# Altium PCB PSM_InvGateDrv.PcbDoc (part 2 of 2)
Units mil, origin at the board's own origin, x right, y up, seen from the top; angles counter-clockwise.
Board outline 5413.39 x 1771.65 mil, 2 copper layers (Top Layer, Bottom Layer), stack 62 mil thick; 130 components, 58 nets, 317 pads, 172 vias.
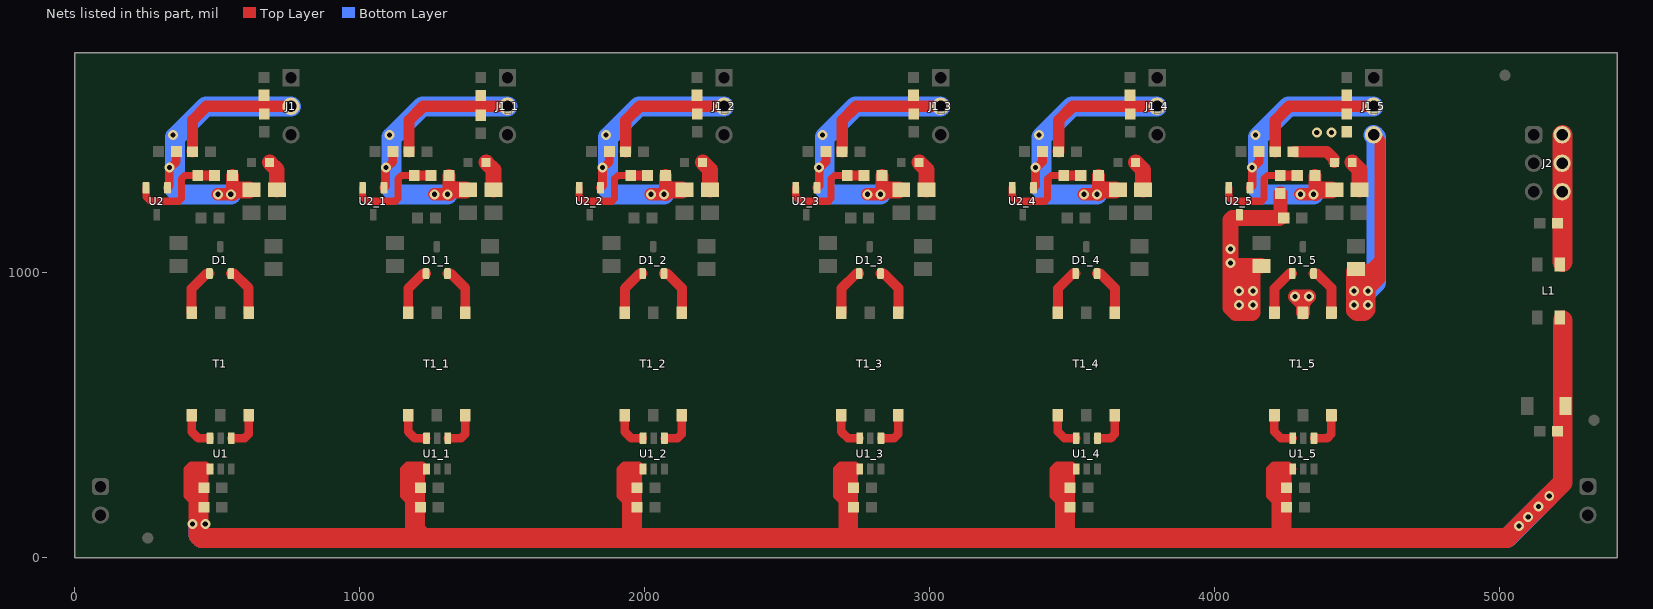
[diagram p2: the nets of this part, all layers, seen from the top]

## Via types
v1: diameter 35, hole 18, Top Layer to Bottom Layer, 172 vias

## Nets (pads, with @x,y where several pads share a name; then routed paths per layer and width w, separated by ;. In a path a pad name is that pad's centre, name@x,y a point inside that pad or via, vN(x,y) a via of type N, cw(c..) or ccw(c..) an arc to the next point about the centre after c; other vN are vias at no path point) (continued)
-4V_6: C4_5.2 C5_5.2 C6_5.2 C7_5.2 C10_5.2 D2_5.1 J1_5.3 R4_5.1 T1_5.5 U2_5.3 | length 2935.9
  Top Layer w40: C6_5.2@4234.67,1200.1 C6_5.2@4243.04,1191.73 ; C10_5.2@4282.41,1424.55 4394.08,1424.55 4420.6,1398.03 D2_5.1@4420.6,1387.15 ; v1(4538.31,935.83) 4580.95,978.46 4580.95,1043.31 ; 4538.31,1004.72 4542.36,1004.72 4580.95,1043.31 ; J1_5.3@4558.63,1484 4580.95,1461.68 4580.95,1043.31
  Top Layer w50: C6_5.2@4226.31,1191.73 4231.33,1196.75 R4_5.1@4231.33,1278.35 ; T1_5.5@4310.26,859.84 4310.26,888.29 ; 4310.26,888.29 4310.26,894.78 v1(4331.62,916.14) v1(4282.41,916.14) 4310.26,888.29
  Top Layer w55: 4085.56,992.91 v1(4085.56,935.83) v1(4085.56,886.61) 4085.56,857.09 ; 4134.77,989.78 v1(4134.77,935.83) v1(4134.77,886.61) 4134.77,859.84 4132.02,857.09 4085.56,857.09 ; C4_5.2@4164.3,1023.78 v1@4056.03,1023.78 ; C6_5.2@4226.31,1191.73 4063.12,1191.73 4056.03,1184.65 v1@4056.03,1023.78 ; v1@4056.03,1023.78 4056.03,876.77 4075.72,857.09 4085.56,857.09 ; 4489.1,866.93 4498.94,857.09 4525.72,857.09 4538.31,869.69 v1(4538.31,886.61) v1(4538.31,935.83) 4538.31,1004.72 4489.1,1004.72 v1(4489.1,935.83) v1(4489.1,886.61) 4489.1,866.93
  Bottom Layer w70: v1(4538.31,935.83) 4567.84,965.35 4567.84,1474.79 J1_5.3@4558.63,1484
  other v1: 4056.03,1034.25 4056.03,1083.46 4359.18,1492.02 4410.76,1492.02
AGND: C2.2 C2_1.2 C2_2.2 C2_3.2 C2_4.2 C2_5.2 C3.2 C3_1.2 C3_2.2 C3_3.2 C3_4.2 C3_5.2 C8.2 C12.2 L1.2 U1.4 U1_1.4 U1_2.4 U1_3.4 U1_4.4 U1_5.4 | length 13894.7
  Top Layer w25: 423.35,187.32 393.83,216.85 393.83,310.83 408.12,325.12 460.24,325.12 U1.4@474.54,310.83 452.88,289.17 C3.2@452.88,245.42 C2.2@452.88,176.52 ; 1183.35,187.32 1153.83,216.85 1153.83,310.83 1168.12,325.12 1220.24,325.12 U1_1.4@1234.54,310.83 1212.88,289.17 C3_1.2@1212.88,245.42 C2_1.2@1212.88,176.52 ; 1943.35,187.32 1913.83,216.85 1913.83,310.83 1928.12,325.12 1980.24,325.12 U1_2.4@1994.54,310.83 1972.88,289.17 C3_2.2@1972.88,245.42 C2_2.2@1972.88,176.52 ; 2703.35,187.32 2673.83,216.85 2673.83,310.83 2688.12,325.12 2740.24,325.12 U1_3.4@2754.54,310.83 2732.88,289.17 C3_3.2@2732.88,245.42 C2_3.2@2732.88,176.52 ; 3463.35,187.32 3433.83,216.85 3433.83,310.83 3448.12,325.12 3500.24,325.12 U1_4.4@3514.54,310.83 3492.88,289.17 C3_4.2@3492.88,245.42 C2_4.2@3492.88,176.52 ; 4223.35,187.32 4193.83,216.85 4193.83,310.83 4208.12,325.12 4260.24,325.12 U1_5.4@4274.54,310.83 4252.88,289.17 C3_5.2@4252.88,245.42 C2_5.2@4252.88,176.52
  Top Layer w70: 434.67,299.19 434.67,176.52 434.67,78.71 444.98,68.41 1222.99,68.41 ; C3_1.2@1193.63,245.42 1193.63,289.35 ; C3_1.2@1194.67,245.42 1194.67,96.73 1222.99,68.41 ; 1954.94,79.05 1954.94,299.53 ; 2714.67,299.19 2714.67,245.42 2714.67,78.71 2724.98,68.41 ; 3474.67,299.19 3474.67,245.42 3474.67,78.71 3484.98,68.41 ; 4234.67,68.41 5026.87,68.41 5222.38,263.91 5222.38,442.91 5222.38,531.5 L1.2@5222.38,832.11 ; 4234.67,299.19 4234.67,245.42 4234.67,78.71 4244.98,68.41 3484.98,68.41 ; 1222.99,68.41 2724.98,68.41 ; 2724.98,68.41 3484.98,68.41
  Bottom Layer w70: 434.67,108.27 434.67,78.71 444.49,68.9 5027.36,68.9 v1(5175,216.54)
  other v1: 5068.9,110.43 413.51,118.11 457.88,118.11 5101.18,142.72 5137.8,179.33
NetC11_2: C11.2 J2.2 J2.4 J2.6 L1.3 | length 446
  Top Layer w70: L1.3@5220.8,1037.97 5220.8,1284 5220.8,1384 J2.2@5220.8,1484
NetD1_1: D1.1 T1.6 | length 168.7
  Top Layer w35: T1.6@410.26,859.84 410.26,944.09 463.02,996.85 D1.1@472.86,996.85
NetD1_1_1: D1_1.1 T1_1.6 | length 168.7
  Top Layer w35: T1_1.6@1170.26,859.84 1170.26,944.09 1223.02,996.85 D1_1.1@1232.86,996.85
NetD1_1_2: D1_1.2 T1_1.4 | length 169.7
  Top Layer w35: D1_1.2@1307.67,996.85 1319.18,996.85 1370.26,945.77 T1_1.4@1370.26,859.84
NetD1_2: D1.2 T1.4 | length 169.7
  Top Layer w35: D1.2@547.67,996.85 559.18,996.85 610.26,945.77 T1.4@610.26,859.84
NetD1_2_1: D1_2.1 T1_2.6 | length 168.7
  Top Layer w35: T1_2.6@1930.26,859.84 1930.26,944.09 1983.02,996.85 D1_2.1@1992.86,996.85
NetD1_2_2: D1_2.2 T1_2.4 | length 169.7
  Top Layer w35: D1_2.2@2067.67,996.85 2079.18,996.85 2130.26,945.77 T1_2.4@2130.26,859.84
NetD1_3_1: D1_3.1 T1_3.6 | length 168.7
  Top Layer w35: T1_3.6@2690.26,859.84 2690.26,944.09 2743.02,996.85 D1_3.1@2752.86,996.85
NetD1_3_2: D1_3.2 T1_3.4 | length 169.7
  Top Layer w35: D1_3.2@2827.67,996.85 2839.18,996.85 2890.26,945.77 T1_3.4@2890.26,859.84
NetD1_4_1: D1_4.1 T1_4.6 | length 168.7
  Top Layer w35: T1_4.6@3450.26,859.84 3450.26,944.09 3503.02,996.85 D1_4.1@3512.86,996.85
NetD1_4_2: D1_4.2 T1_4.4 | length 169.7
  Top Layer w35: D1_4.2@3587.67,996.85 3599.18,996.85 3650.26,945.77 T1_4.4@3650.26,859.84
NetD1_5_1: D1_5.1 T1_5.6 | length 168.7
  Top Layer w35: T1_5.6@4210.26,859.84 4210.26,944.09 4263.02,996.85 D1_5.1@4272.86,996.85
NetD1_5_2: D1_5.2 T1_5.4 | length 169.7
  Top Layer w35: D1_5.2@4347.67,996.85 4359.18,996.85 4410.26,945.77 T1_5.4@4410.26,859.84
NetD2_1_2: D2_1.2 R1_1.1 | length 107
  Top Layer w55: D2_1.2@1443.59,1387.15 1469.18,1361.56 R1_1.1@1469.18,1290.79
NetD2_2: D2.2 R1.1 | length 107
  Top Layer w55: D2.2@683.59,1387.15 709.18,1361.56 R1.1@709.18,1290.79
NetD2_2_2: D2_2.2 R1_2.1 | length 107
  Top Layer w55: D2_2.2@2203.59,1387.15 2229.18,1361.56 R1_2.1@2229.18,1290.79
NetD2_3_2: D2_3.2 R1_3.1 | length 107
  Top Layer w55: D2_3.2@2963.59,1387.15 2989.18,1361.56 R1_3.1@2989.18,1290.79
NetD2_4_2: D2_4.2 R1_4.1 | length 107
  Top Layer w55: D2_4.2@3723.59,1387.15 3749.18,1361.56 R1_4.1@3749.18,1290.79
NetD2_5_2: D2_5.2 R1_5.1 | length 107
  Top Layer w55: D2_5.2@4483.59,1387.15 4509.18,1361.56 R1_5.1@4509.18,1290.79
NetR3_1: R3.1 R4.2 U2.2 | length 350.1
  Top Layer w25: U2.2@250.13,1298.03 250.13,1266.54 265.87,1250.79 364.3,1250.79 374.14,1260.63 374.14,1329.53 385.95,1341.34 R4.2@431.33,1341.34
  Top Layer w35: R4.2@431.33,1341.34 R3.1@484.38,1341.34
NetR3_1_1: R3_1.1 R4_1.2 U2_1.2 | length 350.1
  Top Layer w25: U2_1.2@1010.13,1298.03 1010.13,1266.54 1025.87,1250.79 1124.3,1250.79 1134.14,1260.63 1134.14,1329.53 1145.95,1341.34 R4_1.2@1191.33,1341.34
  Top Layer w35: R4_1.2@1191.33,1341.34 R3_1.1@1244.38,1341.34
NetR3_2_1: R3_2.1 R4_2.2 U2_2.2 | length 350.1
  Top Layer w25: U2_2.2@1770.13,1298.03 1770.13,1266.54 1785.87,1250.79 1884.3,1250.79 1894.14,1260.63 1894.14,1329.53 1905.95,1341.34 R4_2.2@1951.33,1341.34
  Top Layer w35: R4_2.2@1951.33,1341.34 R3_2.1@2004.38,1341.34
NetR3_3_1: R3_3.1 R4_3.2 U2_3.2 | length 350.1
  Top Layer w25: U2_3.2@2530.13,1298.03 2530.13,1266.54 2545.87,1250.79 2644.3,1250.79 2654.14,1260.63 2654.14,1329.53 2665.95,1341.34 R4_3.2@2711.33,1341.34
  Top Layer w35: R4_3.2@2711.33,1341.34 R3_3.1@2764.38,1341.34
NetR3_4_1: R3_4.1 R4_4.2 U2_4.2 | length 350.1
  Top Layer w25: U2_4.2@3290.13,1298.03 3290.13,1266.54 3305.87,1250.79 3404.3,1250.79 3414.14,1260.63 3414.14,1329.53 3425.95,1341.34 R4_4.2@3471.33,1341.34
  Top Layer w35: R4_4.2@3471.33,1341.34 R3_4.1@3524.38,1341.34
NetR3_5_1: R3_5.1 R4_5.2 U2_5.2 | length 350.1
  Top Layer w25: U2_5.2@4050.13,1298.03 4050.13,1266.54 4065.87,1250.79 4164.3,1250.79 4174.14,1260.63 4174.14,1329.53 4185.95,1341.34 R4_5.2@4231.33,1341.34
  Top Layer w35: R4_5.2@4231.33,1341.34 R3_5.1@4284.38,1341.34
NetT1_1: T1.1 U1.3 | length 131.3
  Top Layer w30: T1.1@410.26,500 410.26,442.03 433.2,419.09 U1.3@474.06,419.09
NetT1_1_1: T1_1.1 U1_1.3 | length 131.3
  Top Layer w30: T1_1.1@1170.26,500 1170.26,442.03 1193.2,419.09 U1_1.3@1234.06,419.09
NetT1_1_3: T1_1.3 U1_1.1 | length 132.8
  Top Layer w30: U1_1.1@1309.81,419.09 1355.6,419.09 1370.26,433.76 T1_1.3@1370.26,500
NetT1_2_1: T1_2.1 U1_2.3 | length 131.3
  Top Layer w30: T1_2.1@1930.26,500 1930.26,442.03 1953.2,419.09 U1_2.3@1994.06,419.09
NetT1_2_3: T1_2.3 U1_2.1 | length 132.8
  Top Layer w30: U1_2.1@2069.81,419.09 2115.6,419.09 2130.26,433.76 T1_2.3@2130.26,500
NetT1_3: T1.3 U1.1 | length 132.8
  Top Layer w30: U1.1@549.81,419.09 595.6,419.09 610.26,433.76 T1.3@610.26,500
NetT1_3_1: T1_3.1 U1_3.3 | length 131.3
  Top Layer w30: T1_3.1@2690.26,500 2690.26,442.03 2713.2,419.09 U1_3.3@2754.06,419.09
NetT1_3_3: T1_3.3 U1_3.1 | length 132.8
  Top Layer w30: U1_3.1@2829.81,419.09 2875.6,419.09 2890.26,433.76 T1_3.3@2890.26,500
NetT1_4_1: T1_4.1 U1_4.3 | length 131.3
  Top Layer w30: T1_4.1@3450.26,500 3450.26,442.03 3473.2,419.09 U1_4.3@3514.06,419.09
NetT1_4_3: T1_4.3 U1_4.1 | length 132.8
  Top Layer w30: U1_4.1@3589.81,419.09 3635.6,419.09 3650.26,433.76 T1_4.3@3650.26,500
NetT1_5_1: T1_5.1 U1_5.3 | length 131.3
  Top Layer w30: T1_5.1@4210.26,500 4210.26,442.03 4233.2,419.09 U1_5.3@4274.06,419.09
NetT1_5_3: T1_5.3 U1_5.1 | length 132.8
  Top Layer w30: U1_5.1@4349.81,419.09 4395.6,419.09 4410.26,433.76 T1_5.3@4410.26,500
S_1: C1.2 C7.1 C9.2 C10.1 J1.2 R2.1 R3.2 U2.1 | length 1632.6
  Top Layer w30: U2.1@324.93,1298.03 332.02,1305.12 v1(332.02,1368.72) 336.02,1368.72 356.43,1389.12 C9.2@356.43,1425.54
  Top Layer w40: C10.1@412.04,1425.54 C10.1@413.02,1424.55 413.02,1495.87 413.02,1534.44 462.58,1584 J1.2@758.63,1584
  Top Layer w45: v1(502.09,1275.2) v1(547.37,1275.2) 553.28,1281.1 R3.2@553.28,1341.34
  Top Layer w60: v1@553.28,1281.1 562.96,1290.79 R2.1@610.76,1290.79
  Bottom Layer w70: v1(547.37,1275.2) v1(502.09,1275.2) 369.42,1275.2 352.09,1292.52 352.09,1475.59 460.5,1584 J1.2@758.63,1584
  other v1: 344.49,1483.87
S_2: C1_1.2 C7_1.1 C9_1.2 C10_1.1 J1_1.2 R2_1.1 R3_1.2 U2_1.1 | length 1632.6
  Top Layer w30: U2_1.1@1084.93,1298.03 1092.02,1305.12 v1(1092.02,1368.72) 1096.02,1368.72 1116.43,1389.12 C9_1.2@1116.43,1425.54
  Top Layer w40: C10_1.1@1172.04,1425.54 C10_1.1@1173.02,1424.55 1173.02,1495.87 1173.02,1534.44 1222.58,1584 J1_1.2@1518.63,1584
  Top Layer w45: v1(1262.09,1275.2) v1(1307.37,1275.2) 1313.28,1281.1 R3_1.2@1313.28,1341.34
  Top Layer w60: v1@1313.28,1281.1 1322.96,1290.79 R2_1.1@1370.76,1290.79
  Bottom Layer w70: v1(1307.37,1275.2) v1(1262.09,1275.2) 1129.42,1275.2 1112.09,1292.52 1112.09,1475.59 1220.5,1584 J1_1.2@1518.63,1584
  other v1: 1104.49,1483.87
S_3: C1_2.2 C7_2.1 C9_2.2 C10_2.1 J1_2.2 R2_2.1 R3_2.2 U2_2.1 | length 1632.6
  Top Layer w30: U2_2.1@1844.93,1298.03 1852.02,1305.12 v1(1852.02,1368.72) 1856.02,1368.72 1876.43,1389.12 C9_2.2@1876.43,1425.54
  Top Layer w40: C10_2.1@1932.04,1425.54 C10_2.1@1933.02,1424.55 1933.02,1495.87 1933.02,1534.44 1982.58,1584 J1_2.2@2278.63,1584
  Top Layer w45: v1(2022.09,1275.2) v1(2067.37,1275.2) 2073.28,1281.1 R3_2.2@2073.28,1341.34
  Top Layer w60: v1@2073.28,1281.1 2082.96,1290.79 R2_2.1@2130.76,1290.79
  Bottom Layer w70: v1(2067.37,1275.2) v1(2022.09,1275.2) 1889.42,1275.2 1872.09,1292.52 1872.09,1475.59 1980.5,1584 J1_2.2@2278.63,1584
  other v1: 1864.49,1483.87
S_4: C1_3.2 C7_3.1 C9_3.2 C10_3.1 J1_3.2 R2_3.1 R3_3.2 U2_3.1 | length 1632.6
  Top Layer w30: U2_3.1@2604.93,1298.03 2612.02,1305.12 v1(2612.02,1368.72) 2616.02,1368.72 2636.43,1389.12 C9_3.2@2636.43,1425.54
  Top Layer w40: C10_3.1@2692.04,1425.54 C10_3.1@2693.02,1424.55 2693.02,1495.87 2693.02,1534.44 2742.58,1584 J1_3.2@3038.63,1584
  Top Layer w45: v1(2782.09,1275.2) v1(2827.37,1275.2) 2833.28,1281.1 R3_3.2@2833.28,1341.34
  Top Layer w60: v1@2833.28,1281.1 2842.96,1290.79 R2_3.1@2890.76,1290.79
  Bottom Layer w70: v1(2827.37,1275.2) v1(2782.09,1275.2) 2649.42,1275.2 2632.09,1292.52 2632.09,1475.59 2740.5,1584 J1_3.2@3038.63,1584
  other v1: 2624.49,1483.87
S_5: C1_4.2 C7_4.1 C9_4.2 C10_4.1 J1_4.2 R2_4.1 R3_4.2 U2_4.1 | length 1632.6
  Top Layer w30: U2_4.1@3364.93,1298.03 3372.02,1305.12 v1(3372.02,1368.72) 3376.02,1368.72 3396.43,1389.12 C9_4.2@3396.43,1425.54
  Top Layer w40: C10_4.1@3452.04,1425.54 C10_4.1@3453.02,1424.55 3453.02,1495.87 3453.02,1534.44 3502.58,1584 J1_4.2@3798.63,1584
  Top Layer w45: v1(3542.09,1275.2) v1(3587.37,1275.2) 3593.28,1281.1 R3_4.2@3593.28,1341.34
  Top Layer w60: v1@3593.28,1281.1 3602.96,1290.79 R2_4.1@3650.76,1290.79
  Bottom Layer w70: v1(3587.37,1275.2) v1(3542.09,1275.2) 3409.42,1275.2 3392.09,1292.52 3392.09,1475.59 3500.5,1584 J1_4.2@3798.63,1584
  other v1: 3384.49,1483.87
S_6: C1_5.2 C7_5.1 C9_5.2 C10_5.1 J1_5.2 R2_5.1 R3_5.2 U2_5.1 | length 1632.6
  Top Layer w30: U2_5.1@4124.93,1298.03 4132.02,1305.12 v1(4132.02,1368.72) 4136.02,1368.72 4156.43,1389.12 C9_5.2@4156.43,1425.54
  Top Layer w40: C10_5.1@4212.04,1425.54 C10_5.1@4213.02,1424.55 4213.02,1495.87 4213.02,1534.44 4262.58,1584 J1_5.2@4558.63,1584
  Top Layer w45: v1(4302.09,1275.2) v1(4347.37,1275.2) 4353.28,1281.1 R3_5.2@4353.28,1341.34
  Top Layer w60: v1@4353.28,1281.1 4362.96,1290.79 R2_5.1@4410.76,1290.79
  Bottom Layer w70: v1(4347.37,1275.2) v1(4302.09,1275.2) 4169.42,1275.2 4152.09,1292.52 4152.09,1475.59 4260.5,1584 J1_5.2@4558.63,1584
  other v1: 4144.49,1483.87
pads on no net: FID1.1 FID2.1 FID3.1 J3.1 J3.2 J4.1 J4.2 U1.6 U1_1.6 U1_2.6 U1_3.6 U1_4.6 U1_5.6

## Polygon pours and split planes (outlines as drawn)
5Vs on Top Layer "TOP_LAYER_5VS_P098" (solid, pour order 98): 511.81,265.51 513.44,267.14 610.24,267.14 629.92,247.46 629.92,153.63 615.48,139.19 520.6,139.19 501.97,157.82 501.97,252.45 516.66,267.14
5Vs on Top Layer "TOP_LAYER_5VS_P096" (solid, pour order 96): 1270.63,265.51 1272.26,267.14 1369.06,267.14 1388.74,247.46 1388.74,153.63 1374.3,139.19 1279.42,139.19 1260.79,157.82 1260.79,252.45 1275.48,267.14
5Vs on Top Layer "TOP_LAYER_5VS_P094" (solid, pour order 94): 2029.45,265.51 2031.08,267.14 2127.87,267.14 2147.56,247.46 2147.56,153.63 2133.12,139.19 2038.24,139.19 2019.61,157.82 2019.61,252.45 2034.3,267.14
5Vs on Top Layer "TOP_LAYER_5VS_P092" (solid, pour order 92): 2788.27,265.51 2789.9,267.14 2886.69,267.14 2906.38,247.46 2906.38,153.63 2891.94,139.19 2797.06,139.19 2778.43,157.82 2778.43,252.45 2793.12,267.14
5Vs on Top Layer "TOP_LAYER_5VS_P090" (solid, pour order 90): 3547.09,264.12 3548.72,265.75 3645.51,265.75 3665.2,246.06 3665.2,152.24 3650.76,137.8 3555.87,137.8 3537.24,156.43 3537.24,251.06 3551.94,265.75
5Vs on Top Layer "TOP_LAYER_5VS_P086" (solid, pour order 86): 4335.43,265.75 4852.36,265.75 5048.17,461.56 5167.32,460.8 5167.32,344.49 4960.63,137.8 4344.76,137.8 4306.03,176.52 4306.03,236.35
-4V_6 on Top Layer "TOP_LAYER_-4V_6_P080" (solid, pour order 80): 4568,1515.75 4587.53,1496.22 4587.53,1427.17 4565.23,1404.87 4279.91,1404.87 4262.37,1422.41 4262.37,1474.12 4304.5,1515.75
S_6 on Top Layer "Top Layer-S_1" (solid, pour order 78): 4579.39,1535.72 4608.63,1564.96 4608.63,1620.22 4587.53,1641.32 4161.13,1641.32 4134.77,1614.96 4134.77,1385.43 4152.09,1368.11 4223.23,1368.11 4242.91,1387.8 4242.91,1512.77 4265.57,1535.43 4577.28,1535.43 4577.56,1535.72
+15V_6 on Top Layer "TOP_LAYER_+15V_6_P076" (solid, pour order 76): 4026.38,1368.11 4097.05,1368.11 4114.96,1386.02 4114.96,1621.64 4146.87,1653.54 4588.94,1653.54 4608.63,1673.23 4608.63,1723.37 4598,1734 4077.31,1734 4016.54,1673.23 4016.54,1377.95
-4V_5 on Top Layer "TOP_LAYER_-4V_5_P070" (solid, pour order 70): 3808,1515.75 3827.53,1496.22 3827.53,1427.17 3805.23,1404.87 3519.91,1404.87 3502.37,1422.41 3502.37,1474.12 3544.5,1515.75
S_5 on Top Layer "Top Layer-S_1" (solid, pour order 68): 3819.39,1535.72 3848.63,1564.96 3848.63,1620.22 3827.53,1641.32 3401.13,1641.32 3374.77,1614.96 3374.77,1385.43 3392.09,1368.11 3463.23,1368.11 3482.91,1387.8 3482.91,1512.77 3505.57,1535.43 3817.28,1535.43 3817.56,1535.72
+15V_5 on Top Layer "TOP_LAYER_+15V_5_P066" (solid, pour order 66): 3266.38,1368.11 3337.05,1368.11 3354.96,1386.02 3354.96,1621.64 3386.87,1653.54 3828.94,1653.54 3848.63,1673.23 3848.63,1723.37 3838,1734 3317.31,1734 3256.54,1673.23 3256.54,1377.95
-4V_4 on Top Layer "TOP_LAYER_-4V_4_P060" (solid, pour order 60): 3048,1515.75 3067.53,1496.22 3067.53,1427.17 3045.23,1404.87 2759.91,1404.87 2742.37,1422.41 2742.37,1474.12 2784.5,1515.75
S_4 on Top Layer "Top Layer-S_1" (solid, pour order 58): 3059.39,1535.72 3088.63,1564.96 3088.63,1620.22 3067.53,1641.32 2641.13,1641.32 2614.77,1614.96 2614.77,1385.43 2632.09,1368.11 2703.23,1368.11 2722.91,1387.8 2722.91,1512.77 2745.57,1535.43 3057.28,1535.43 3057.56,1535.72
+15V_4 on Top Layer "TOP_LAYER_+15V_4_P056" (solid, pour order 56): 2506.38,1368.11 2577.05,1368.11 2594.96,1386.02 2594.96,1621.64 2626.87,1653.54 3068.94,1653.54 3088.63,1673.23 3088.63,1723.37 3078,1734 2557.31,1734 2496.54,1673.23 2496.54,1377.95
-4V_3 on Top Layer "TOP_LAYER_-4V_3_P050" (solid, pour order 50): 2288,1515.75 2307.53,1496.22 2307.53,1427.17 2285.23,1404.87 1999.91,1404.87 1982.37,1422.41 1982.37,1474.12 2024.5,1515.75
S_3 on Top Layer "Top Layer-S_3" (solid, pour order 48): 2299.39,1535.72 2328.63,1564.96 2328.63,1620.22 2307.53,1641.32 1881.13,1641.32 1854.77,1614.96 1854.77,1385.43 1872.09,1368.11 1943.23,1368.11 1962.91,1387.8 1962.91,1512.77 1985.57,1535.43 2297.28,1535.43 2297.56,1535.72
+15V_3 on Top Layer "TOP_LAYER_+15V_3_P046" (solid, pour order 46): 1746.38,1368.11 1817.05,1368.11 1834.96,1386.02 1834.96,1621.64 1866.87,1653.54 2308.94,1653.54 2328.63,1673.23 2328.63,1723.37 2318,1734 1797.31,1734 1736.54,1673.23 1736.54,1377.95
-4V_2 on Top Layer "TOP_LAYER_-4V_2_P030" (solid, pour order 30): 1528,1515.75 1547.53,1496.22 1547.53,1427.17 1525.23,1404.87 1239.91,1404.87 1222.37,1422.41 1222.37,1474.12 1264.5,1515.75
S_2 on Top Layer "TOP_LAYER_S_2_P028" (solid, pour order 28): 1539.39,1535.72 1568.63,1564.96 1568.63,1620.22 1547.53,1641.32 1121.13,1641.32 1094.77,1614.96 1094.77,1385.43 1112.09,1368.11 1183.23,1368.11 1202.91,1387.8 1202.91,1512.77 1225.57,1535.43 1537.28,1535.43 1537.56,1535.72
+15V_2 on Top Layer "TOP_LAYER_+15V_2_P026" (solid, pour order 26): 986.38,1368.11 1057.05,1368.11 1074.96,1386.02 1074.96,1621.64 1106.87,1653.54 1548.94,1653.54 1568.63,1673.23 1568.63,1723.37 1558,1734 1037.31,1734 976.54,1673.23 976.54,1377.95
+15V_1 on Top Layer "TOP_LAYER_+15V_1_P024" (solid, pour order 24): 226.38,1368.11 297.05,1368.11 314.96,1386.02 314.96,1621.64 346.87,1653.54 788.94,1653.54 808.63,1673.23 808.63,1723.37 798,1734 277.31,1734 216.54,1673.23 216.54,1377.95
S_1 on Top Layer "Top Layer-S_1" (solid, pour order 20): 779.39,1535.72 808.63,1564.96 808.63,1620.22 787.53,1641.32 361.13,1641.32 334.77,1614.96 334.77,1385.43 352.09,1368.11 423.23,1368.11 442.91,1387.8 442.91,1512.77 465.57,1535.43 777.28,1535.43 777.56,1535.72
-4V_1 on Top Layer "TOP_LAYER_-4V_1_P000" (solid, pour order 0): 768,1515.75 787.53,1496.22 787.53,1427.17 765.23,1404.87 479.91,1404.87 462.37,1422.41 462.37,1474.12 504.5,1515.75
5Vs on Bottom Layer "BOTTOM_LAYER_5VS_P088" (solid, pour order 88): 4413.52,295.28 4448.82,268.8 4448.82,157.24 4422.89,137.8 586.84,137.79 561.02,163.61 561.02,255.91 600.39,295.28
-4V_6 on Bottom Layer "Bottom Layer--4V_1" (solid, pour order 84): 4075.72,1103.15 4213.51,965.35 4410.36,965.35 4479.26,1034.25 4587.53,1034.25 4617.06,1004.72 4617.06,857.09 4597.37,837.4 4036.35,837.4 4016.66,857.09 4016.66,1083.46 4036.35,1103.15
-4V_6 on Bottom Layer "BOTTOM_LAYER_-4V_6_P082" (solid, pour order 82): 4566.85,1516.88 4586.38,1497.35 4586.38,1435.98 4556.39,1406 4278.76,1406 4261.22,1423.54 4261.22,1475.25 4303.35,1516.88
-4V_5 on Bottom Layer "Bottom Layer--4V_1" (solid, pour order 74): 3315.72,1103.15 3453.51,965.35 3650.36,965.35 3719.26,1034.25 3827.53,1034.25 3857.06,1004.72 3857.06,857.09 3837.37,837.4 3276.35,837.4 3256.66,857.09 3256.66,1083.46 3276.35,1103.15
-4V_5 on Bottom Layer "BOTTOM_LAYER_-4V_5_P072" (solid, pour order 72): 3806.85,1516.88 3826.38,1497.35 3826.38,1435.98 3796.39,1406 3518.76,1406 3501.22,1423.54 3501.22,1475.25 3543.35,1516.88
-4V_4 on Bottom Layer "Bottom Layer--4V_1" (solid, pour order 64): 2555.72,1103.15 2693.51,965.35 2890.36,965.35 2959.26,1034.25 3067.53,1034.25 3097.06,1004.72 3097.06,857.09 3077.37,837.4 2516.35,837.4 2496.66,857.09 2496.66,1083.46 2516.35,1103.15
-4V_4 on Bottom Layer "BOTTOM_LAYER_-4V_4_P062" (solid, pour order 62): 3046.85,1516.88 3066.38,1497.35 3066.38,1435.98 3036.39,1406 2758.76,1406 2741.22,1423.54 2741.22,1475.25 2783.35,1516.88
-4V_3 on Bottom Layer "Bottom Layer--4V_1" (solid, pour order 54): 1795.72,1103.15 1933.51,965.35 2130.36,965.35 2199.26,1034.25 2307.53,1034.25 2337.06,1004.72 2337.06,857.09 2317.37,837.4 1756.35,837.4 1736.66,857.09 1736.66,1083.46 1756.35,1103.15
-4V_3 on Bottom Layer "BOTTOM_LAYER_-4V_3_P052" (solid, pour order 52): 2286.85,1516.88 2306.38,1497.35 2306.38,1435.98 2276.39,1406 1998.76,1406 1981.22,1423.54 1981.22,1475.25 2023.35,1516.88
-4V_2 on Bottom Layer "Bottom Layer--4V_1" (solid, pour order 34): 1035.72,1103.15 1173.51,965.35 1370.36,965.35 1439.26,1034.25 1547.53,1034.25 1577.06,1004.72 1577.06,857.09 1557.37,837.4 996.35,837.4 976.66,857.09 976.66,1083.46 996.35,1103.15
-4V_2 on Bottom Layer "BOTTOM_LAYER_-4V_2_P032" (solid, pour order 32): 1526.85,1516.88 1546.38,1497.35 1546.38,1435.98 1516.39,1406 1238.76,1406 1221.22,1423.54 1221.22,1475.25 1263.35,1516.88
-4V_1 on Bottom Layer "BOTTOM_LAYER_-4V_1_P022" (solid, pour order 22): 766.85,1516.88 786.38,1497.35 786.38,1435.98 756.39,1406 478.76,1406 461.22,1423.54 461.22,1475.25 503.35,1516.88
-4V_1 on Bottom Layer "Bottom Layer--4V_1" (solid, pour order 6): 275.72,1103.15 413.51,965.35 610.36,965.35 679.26,1034.25 787.53,1034.25 817.06,1004.72 817.06,857.09 797.37,837.4 236.35,837.4 216.66,857.09 216.66,1083.46 236.35,1103.15

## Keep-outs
Keep-Out Layer:
  text ".Layer_Name" at 577,-850.08 h60

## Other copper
Top Layer:
  text ".Layer_Name" at 577,-850.08 h60
Bottom Layer:
  text ".Layer_Name" at 577,-850.08 h60

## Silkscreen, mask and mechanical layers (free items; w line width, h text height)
Top Overlay:
  lines w10: 215.87,1515.5 215.87,1733.34 ; 216.66,275.91 216.66,531.81 364.3,531.81 ; 216.66,1368.11 216.66,827.09 364.3,827.09 ; 639.89,531.81 807.21,531.81 807.21,272.62 ; 649.73,827.09 807.21,827.09 807.21,1410.54 ; 975.87,1515.5 975.87,1733.34 ; 976.66,275.91 976.66,531.81 1124.3,531.81 ; 976.66,1368.11 976.66,827.09 1124.3,827.09 ; 1399.89,531.81 1567.21,531.81 1567.21,272.62 ; 1409.73,827.09 1567.21,827.09 1567.21,1410.54 ; 1735.87,1515.5 1735.87,1733.34 ; 1736.66,275.91 1736.66,531.81 1884.3,531.81 ; 1736.66,1368.11 1736.66,827.09 1884.3,827.09 ; 2159.89,531.81 2327.21,531.81 2327.21,272.62 ; 2169.73,827.09 2327.21,827.09 2327.21,1410.54 ; 2495.87,1515.5 2495.87,1733.34 ; 2496.66,275.91 2496.66,531.81 2644.3,531.81 ; 2496.66,1368.11 2496.66,827.09 2644.3,827.09 ; 2919.89,531.81 3087.21,531.81 3087.21,272.62 ; 2929.73,827.09 3087.21,827.09 3087.21,1410.54 ; 3255.87,1515.5 3255.87,1733.34 ; 3256.66,275.91 3256.66,531.81 3404.3,531.81 ; 3256.66,1368.11 3256.66,827.09 3404.3,827.09 ; 3679.89,531.81 3847.21,531.81 3847.21,272.62 ; 3689.73,827.09 3847.21,827.09 3847.21,1410.54 ; 4015.87,1515.5 4015.87,1733.34 ; 4016.66,275.91 4016.66,531.81 4164.3,531.81 ; 4016.66,1368.11 4016.66,827.09 4164.3,827.09 ; 4439.89,531.81 4607.21,531.81 4607.21,272.62 ; 4449.73,827.09 4607.21,827.09 4607.21,1410.54
  text "+5V GND" at 5039.37,1585.97 h40
  text "VEE GND VCC" at 4675.2,1377.95 h35 r90
  text "VEE GND VCC" at 1633.86,1370.46 h35 r90
  text "VEE GND VCC" at 2391.73,1370.46 h35 r90
  text "VEE GND VCC" at 3149.61,1370.46 h35 r90
  text "VEE GND VCC" at 3917.32,1370.46 h35 r90
  text "VEE GND VCC" at 866.14,1368.11 h35 r90
  text "High Voltage" at 4833.44,1045.2 h110 r90
  text "Power Supply - Inverter Gate Driver" at 125,377.66 h90 r90
  text ".Layer_Name" at 577,-850.08 h60
Bottom Overlay:
  text "High Voltage" at 4289.37,653.66 h110
  text ".Layer_Name" at 577,-850.08 h60
Top Paste:
  text ".Layer_Name" at 577,-850.08 h60
Bottom Paste:
  text ".Layer_Name" at 577,-850.08 h60
Top Solder:
  text ".Layer_Name" at 577,-850.08 h60
  text ".Layer_Name" at 577,-850.08 h60
Bottom Solder:
  text ".Layer_Name" at 577,-850.08 h60
Drill Guide:
  text ".Layer_Name" at 577,-850.08 h60
M1 Board Outline:
  the board outline again, w10
  text ".Layer_Name" at 577,-850.08 h60
M2 Board Dimensions:
  rectangle: 0,-266.59 125,-141.59
  rectangle: 125,-391.59 500,-266.59
  lines w7: 0,-266.59 1000,-266.59 ; 125,-391.59 125,-141.59 ; 250,-391.59 250,-141.59 ; 500,-391.59 500,-141.59 ; 750,-391.59 750,-141.59 ; 0,-391.59 1000,-391.59 1000,-141.59 0,-141.59 0,-391.59
  text ".Layer_Name" at 577,-850.08 h60
M3 3D STEP Top:
  text ".Layer_Name" at 577,-850.08 h60
M4 3D STEP Bottom:
  text ".Layer_Name" at 577,-850.08 h60
M5 Assembly Top:
  lines w10: -292,-921.76 6308,-921.76 ; -292,-718.42 6310,-718.42 ; -292,-515.09 -292,-1125.09 3713,-1125.09 6310,-1125.09 6310,-515.09 -291.5,-515.09 -291.5,-1125.09 1284,-1125.09 ; 2173,-1125.09 2173,-515.09 ; 3440,-718.42 3440,-515.09 ; 4280,-718.42 4280,-515.09 ; 4902,-1131.59 4902,-928.76
  text "COMPONENTS MARKED 'DNP' SHOULD NOT BE POPULATED." at 1153.5,-310.09 h60
  text "ASSEMBLY VARIANT:" at 1153,-425.59 h60
  text ".VariantName" at 2189,-425.59 h60
  text "PCB VIEWED FROM TOP SIDE" at -228.5,-647.26 h60
  text "BOARD #:" at 2248,-647.26 h60
  text ".PRJ_Number" at 2793.5,-647.26 h60
  text "REV:" at 3638,-647.26 h60
  text ".PCB_Rev" at 3929.5,-647.26 h60
  text "SVN REV:" at 4476,-647.26 h60
  text ".VersionControl_RevNumber" at 4982,-647.26 h60
  text "TID #:" at 2248,-850.59 h60
  text ".TID" at 2793.5,-850.59 h60
  text "PLOT NAME =" at -228.5,-1055.93 h60
  text ".plot_File_Name" at 577,-1055.93 h60
  text "GENERATED    :" at 2250,-1055.93 h60
  text ".Print_Date" at 3119.5,-1055.93 h60
  text ".Print_Time" at 3848.5,-1055.93 h60
  text "TEXAS INSTRUMENTS" at 5113,-1055.93 h60
M6 Assembly Bottom:
  lines w10: -292.5,-718.92 6309.5,-718.92 ; -290.5,-922.26 6309.5,-922.26 ; 1115.5,-1132.09 1115.5,-929.26 ; 1737.5,-718.92 1737.5,-515.59 ; 2577.5,-718.92 2577.5,-515.59 ; 3844.5,-1125.59 3844.5,-515.59 ; 4733.5,-1125.59 6309,-1125.59 6309,-515.59 -292.5,-515.59 -292.5,-1125.59 2304.5,-1125.59 6309.5,-1125.59 6309.5,-515.59
  text "COMPONENTS MARKED 'DNP' SHOULD NOT BE POPULATED." at 6102,-309.59 h60
  text ".VariantName" at 5058,-425.59 h60
  text "ASSEMBLY VARIANT:" at 6097,-425.59 h60
  text ".VersionControl_RevNumber" at 1035.5,-647.76 h60
  text "SVN REV:" at 1541.5,-647.76 h60
  text ".PCB_Rev" at 2088,-647.76 h60
  text "REV:" at 2379.5,-647.76 h60
  text ".PRJ_Number" at 3224,-647.76 h60
  text "BOARD #:" at 3769.5,-647.76 h60
  text "PCB VIEWED FROM BOTTOM SIDE" at 6246,-647.76 h60
  text ".TID" at 3224,-851.09 h60
  text "TID #:" at 3769.5,-851.09 h60
  text "TEXAS INSTRUMENTS" at 904.5,-1056.43 h60
  text ".Print_Time" at 2169,-1056.43 h60
  text ".Print_Date" at 2898,-1056.43 h60
  text "GENERATED    :" at 3767.5,-1056.43 h60
  text ".plot_File_Name" at 5440.5,-1056.43 h60
  text "PLOT NAME =" at 6246,-1056.43 h60
M9 Title Sheet:
  drawing of 57 lines, arcs and shapes, not listed
  text "1" at 739.84,8044.91 h70
  text "2" at 3235.5,8044.91 h70
  text "3" at 5724.84,8044.91 h70
  text "4" at 8231.51,8044.91 h70
  text "5" at 10730.5,8044.91 h70
  text "6" at 13235.5,8044.91 h70
  text "A" at -416.5,6901.91 h70
  text "A" at 14383.5,6901.91 h70
  text "B" at -416.5,4521.91 h70
  text "B" at 14383.5,4521.91 h70
  text "C" at -416.5,2146.91 h70
  text "C" at 14383.5,2146.91 h70
  text "PROJECT TITLE:" at 11343.5,285.91 h45
  text ".PRJ_Title" at 11393.5,152.58 h70
  text "DESIGNED FOR:" at 11343.5,-15.09 h45
  text ".PRJ_Customer" at 11393.5,-155.09 h70
  text "D" at -416.5,-223.09 h70
  text "D" at 14383.5,-223.09 h70
  text "FILE NAME:" at 11343.5,-315.09 h45
  text ".PCB_File_Name_No_Path" at 11393.5,-435.09 h70
  text "Texas Instruments (TI) and/or its licensors do not warrant the accuracy or completeness of this specification" at 6374,-596.93 h45
  text "ENGINEER:" at 11343.5,-605.09 h45
  text "LAYOUT BY:" at 12848.5,-605.09 h45
  text "or any information contained therein. TI and/or its licensors do not warrant that this design will meet" at 6329.01,-709.59 h45
  text ".PRJ_Engineer" at 11393.5,-760.08 h70
  text ".PCB_Layout" at 12899,-760.08 h70
  text "the specifications, will be suitable for your application or fit for any particular purpose, or will operate in" at 6329.01,-822.26 h45
  text ".Layer_Name" at 577,-850.08 h60
  text "ALTIUM DESIGNER VERSION:" at 12848.5,-915.09 h45
  text "an implementation. TI and/or its licensors do not warrant that the design is production worthy. You should" at 6329.01,-934.93 h45
  text "completely validate and test your design implementation to confirm the system functionality for your application." at 6374,-1047.59 h45
  text ".print_Scale" at 11393.5,-1048.42 h70
  text ".Application_BuildNumber" at 12899,-1048.42 h70
  text "1" at 739.84,-1255.09 h70
  text "2" at 3235.5,-1255.09 h70
  text "3" at 5724.84,-1255.09 h70
  text "4" at 8231.51,-1255.09 h70
  text "5" at 10730.5,-1255.09 h70
  text "6" at 13235.5,-1255.09 h70
M10 Fab Notes:
  drawing of 189 lines, arcs and shapes, not listed
  text "DESIGN INFORMATION" at 12382.02,6364.58 h60
  text "MIN. TRACK WIDTH:" at 11737.46,6232.46 h60
  text "8" at 12833.7,6232.46 h60
  text "MIL" at 12988.46,6232.46 h60
  text "MIN. CLEARANCE:" at 11737.46,6108.33 h60
  text "0.2" at 12773.7,6108.33 h60
  text "mm" at 12988.46,6108.33 h60
  text "MIN. VIA PAD SIZE:" at 11737.46,5984.21 h60
  text "24" at 12803.71,5984.21 h60
  text "MIL" at 12988.46,5984.21 h60
  text "0.05mm (2MIL)" at 12432.46,5854.31 h60
  text "MINIMUM ANNULAR RING" at 11408.23,5846.08 h60
  text "EXTERNAL" at 13140.46,5846.08 h60
  text "PER" at 11608.23,5735.96 h60
  text "IPC-D-275 CLASS 2 LEVEL C" at 11828.23,5735.95 h60
  text "MIL, HOLES" at 13316.46,5635.48 h60
  text "+/-" at 12924,5626.89 h60
  text "+/-" at 13778,5626.89 h60
  text "REGISTRATION TOLERANCES:" at 11408.23,5625.83 h60
  text "METAL" at 12608,5625.83 h60
  text "5" at 13184.2,5625.83 h60
  text "3" at 14017.2,5625.83 h60
  text "MIL" at 14133.46,5625.83 h60
  text "HOLE SIZE TOLERANCE (UNLESS OTHERWISE SPECIFIED):" at 11408.23,5527.51 h60
  text "+/-" at 13778,5524.64 h60
  text "3" at 14017.2,5523.58 h60
  text "MIL" at 14133.46,5523.58 h60
  text "MATERIAL:" at 11333.46,5385.93 h60
  text "FR-4 High Tg" at 12319.9,5257.4 h60
  text "X" at 12175.46,5249.42 h60
  text "FR-408" at 11754.46,5244.9 h60
  text "OTHER" at 13242.46,5244.9 h60
  text "62 MIL (1.6mm) +/-10%" at 12074.56,5101.87 h60
  text "X" at 11954.46,5099.42 h60
  text "THICKNESS:" at 11408.23,5093.65 h60
  text "OTHER" at 13359.46,5093.65 h60
  text "TOLERANCE:" at 11408.23,4955.33 h60
  text "X" at 12256.46,4955.33 h60
  text "ANSI IPC-6012 TYPE 3 CLASS 2" at 12434.48,4955.33 h60
  text "OTHER +/-" at 12434.46,4811.14 h60
  text "BOW & TWIST:" at 11408.23,4665.95 h60
  text "X" at 12256.46,4665.95 h60
  text "ANSI IPC-6012 TYPE 3 CLASS 2" at 12434.48,4665.95 h60
  text "OTHER +/-" at 12434.46,4519.26 h60
  text "DRILLING:" at 11333.46,4388.64 h60
  text "NC_DRILL FILES" at 13094.46,4283.45 h60
  text "REFERENCE:" at 11408.23,4279.51 h60
  text "X" at 12065.46,4279.42 h60
  text "AS SHOWN" at 12243.46,4279.51 h60
  text "X" at 12966.46,4279.51 h60
  text "OTHER" at 13392.46,4137.26 h60
  text "PTH COPPER THICKNESS:" at 11407.91,4133.73 h60
  text "X" at 12547.14,4133.73 h60
  text "20-30 um" at 12675.14,4133.73 h60
  text "BOARD FINISH:" at 11333.46,3986.13 h60
  text "SILKSCREEN:" at 11488.68,3876.01 h60
  text "X" at 12446.46,3876.01 h60
  text "TOP" at 12563.46,3876.01 h60
  text "X" at 12956.46,3876.01 h60
  text "BOTTOM" at 13074.46,3876.01 h60
  text "SILKSCREEN COLOR:" at 11488.68,3720.82 h60
  text "X" at 12445.46,3720.82 h60
  text "WHITE" at 12563.46,3720.82 h60
  text "OTHER" at 13074.46,3720.82 h60
  text "X" at 12576.46,3577.37 h60
  text "GREEN" at 12694.46,3577.37 h60
  text "OTHER" at 13312.46,3577.37 h60
  text "SOLDER RESIST COLOR:" at 11488.68,3570.5 h60
  text "X" at 12576.46,3423.12 h60
  text "MATTE" at 12694.46,3423.12 h60
  text "SEMI-GLOSS" at 13312,3422.48 h60
  text "IMMERSION GOLD (ENIG)" at 12394.46,3250.35 h60
  text "ENEPIG" at 13732,3243.13 h60
  text "SURFACE FINISH:" at 11333.46,3242.13 h60
  text "X" at 12216.46,3242.13 h60
  text "IMM. TIN/SILVER OR EQUIV" at 11663,3104.81 h60
  text "OTHER" at 13094.46,3100.87 h60
  text "ARRAY/PANEL:" at 11333.46,2945.5 h60
  text "CUT AND TRIM PER M1 BOARD OUTLINE" at 12394.46,2937.28 h60
  text "N.C. ROUTE" at 12394.46,2801.31 h60
  text "X" at 13082.46,2801.31 h60
  text "V. SCORE" at 13260.46,2801.31 h60
  text "CERTIFICATION:" at 11333.46,2672.18 h60
  text "MATERIALS AND WORKMANSHIP FOR ALL PCBS" at 12058.46,2672.18 h60
  text "TO MEET OR EXCEED THE REQUIREMENTS OF:" at 12058.46,2578.12 h60
  text "X" at 11695.97,2449.49 h60
  text "ANSI IPC-A-600F CLASS ->" at 11823.96,2449.49 h60
  text "X" at 13471.97,2449.49 h60
  text "2" at 13581.96,2449.49 h60
  text "1" at 13266.96,2447.99 h60
  text "3" at 13935.96,2447.99 h60
  text "X" at 12507.97,2301.8 h60
  text "RoHS" at 12635.96,2301.8 h60
  text "OTHER" at 13280.36,2301.8 h60
  text "PER ORDER" at 13677.42,2301.8 h60
  text "ALL BOARDS MUST MEET OR EXCEED UL94-V0 REQUIREMENTS." at 11361,2147.98 h60
  text "PCB MUST BEAR THE UL94V-0 UL REGISTERED MATERIAL ID NUMBER" at 11361,2031.91 h60
  text "ADDITIONAL REQUIREMENTS:" at 11333.46,1862.49 h60
  text "MICROSECTION:" at 11408.23,1755.36 h60
  text "YES" at 12313.96,1755.36 h60
  text "REQUIRED" at 13175.46,1611.03 h60
  text "BARE BOARD ELEC. TEST:" at 11408.23,1608.17 h60
  text "NONE" at 12713.96,1608.17 h60
  text "X" at 13057.46,1608.17 h60
  text "PER ORDER" at 13767.46,1608.17 h60
  text "XX MIL VIAS REQUIRE NON-CONDUCTIVE FILL AND PLANARIZE" at 11576.38,1403.23 h59
  text "XX MIL VIAS REQUIRE CONDUCTIVE FILL AND PLANARIZE" at 11584.38,1299.25 h60
  text "OUTER XX MIL TRACES REQUIRE 50 OHM SINGLE-ENDED IMPEDANCE" at 11583.39,1135.87 h58
  text "LAYER 2 & 3 (INNER LAYERS) XX MIL WIDE, XX MIL SPACE / TRACES REQUIRE 100 OHM DIFFERENTIAL IMPEDANCE" at 11575.39,900.15 h60
  text ".Layer_Name" at 577,-850.08 h60
M11 Gerber Information:
  lines w10: -292,-921.76 6308,-921.76 ; -292,-718.42 6310,-718.42 ; -292,-515.09 -292,-1125.09 3713,-1125.09 6310,-1125.09 6310,-515.09 -291.5,-515.09 -291.5,-1125.09 1284,-1125.09 ; 2173,-1125.09 2173,-515.09 ; 3440,-718.42 3440,-515.09 ; 4280,-718.42 4280,-515.09 ; 4902,-1131.59 4902,-928.76
  text "ALL ARTWORK VIEWED FROM TOP SIDE" at -228.5,-647.26 h60
  text "BOARD #:" at 2248,-647.26 h60
  text ".PRJ_Number" at 2793.5,-647.26 h60
  text "REV:" at 3638,-647.26 h60
  text ".PCB_Rev" at 3929.5,-647.26 h60
  text "SVN REV:" at 4476,-647.26 h60
  text ".VersionControl_RevNumber" at 4982,-647.26 h60
  text "LAYER NAME =" at -228.5,-850.08 h60
  text "TID #:" at 2248,-850.59 h60
  text ".TID" at 2793.5,-850.59 h60
  text "PLOT NAME =" at -228.5,-1055.93 h60
  text ".plot_File_Name" at 577,-1055.93 h60
  text "GENERATED    :" at 2250,-1055.93 h60
  text ".Print_Date" at 3119.5,-1055.93 h60
  text ".Print_Time" at 3848.5,-1055.93 h60
  text "TEXAS INSTRUMENTS" at 5113,-1055.93 h60
M12 Stackup:
  drawing of 191 lines, arcs and shapes, not listed
  text "Layer" at 9811.59,7455.85 h60
  text "Name" at 10221.51,7455.85 h60
  text "Material" at 11151.25,7455.85 h60
  text "Thickness" at 12011.02,7455.85 h60
  text "Constant" at 12660.85,7455.85 h60
  text "Board Layer Stack" at 13230.71,7455.85 h60
  text "1" at 9811.59,7335.85 h60
  text "Top Overlay" at 10221.51,7335.85 h60
  text "2" at 9811.59,7215.85 h60
  text "Top Solder" at 10221.51,7215.85 h60
  text "Solder Resist" at 11151.25,7215.85 h60
  text "0.40mil" at 12011.02,7215.85 h60
  text "3.5" at 12660.85,7215.85 h60
  text "3" at 9811.59,7095.85 h60
  text "Top Layer" at 10221.51,7095.85 h60
  text "Copper" at 11151.25,7095.85 h60
  text "1.40mil" at 12011.02,7095.85 h60
  text "4" at 9811.59,6975.85 h60
  text "Dielectric1" at 10221.51,6975.85 h60
  text "FR-4" at 11151.25,6975.85 h60
  text "59.20mil" at 12011.02,6975.85 h60
  text "4.8" at 12660.85,6975.85 h60
  text "5" at 9811.59,6855.85 h60
  text "Bottom Layer" at 10221.51,6855.85 h60
  text "Copper" at 11151.25,6855.85 h60
  text "1.40mil" at 12011.02,6855.85 h60
  text "6" at 9811.59,6735.85 h60
  text "Bottom Solder" at 10221.51,6735.85 h60
  text "Solder Resist" at 11151.25,6735.85 h60
  text "0.40mil" at 12011.02,6735.85 h60
  text "3.5" at 12660.85,6735.85 h60
  text "7" at 9811.59,6615.85 h60
  text "Bottom Overlay" at 10221.51,6615.85 h60
  text ".Layer_Name" at 577,-850.08 h60
M13 Component Bodies Top:
  text ".Layer_Name" at 577,-850.08 h60
M14 Component Bodies Bottom:
  text ".Layer_Name" at 577,-850.08 h60
M15 Courtyards Top:
  text ".Layer_Name" at 577,-850.08 h60
M16 Courtyards Bottom:
  text ".Layer_Name" at 577,-850.08 h60
Drill Drawing:
  circle w10: c5363.72,3418.69 r27.63
  lines w10: 5336.09,3142.43 5391.34,3142.43 5391.34,3197.68 5336.09,3197.68 5336.09,3142.43 ; 5336.09,3280.56 5349.9,3280.56 5363.72,3266.75 5377.53,3280.56 5391.34,3280.56 5377.53,3294.37 5391.34,3308.19 5377.53,3308.19 5363.72,3322 5349.9,3308.19 5336.09,3308.19 5349.9,3294.37 5336.09,3280.56
  lines w12: 5286,3105.13 8517.49,3105.13 ; 5286,3478.09 8517.49,3478.09 ; 5623.86,2980.81 5623.86,3602.41 ; 5955.86,2980.81 5955.86,3602.41 ; 6592.43,2980.81 6592.43,3602.41 ; 6851.57,2980.81 6851.57,3602.41 ; 7226.72,2980.81 7226.72,3602.41 ; 7951.05,2980.81 7951.05,3602.41 ; 5286,2980.81 8517.49,2980.81 8517.49,3602.41 5286,3602.41 5286,2980.81
  text "Symbol" at 5360.59,3515.39 h72
  text "Quantity" at 5661.16,3515.39 h72
  text "Finished Hole Size" at 5993.16,3515.39 h72
  text "Plated" at 6629.72,3515.39 h72
  text "Hole Type" at 6888.86,3515.39 h72
  text "Drill Layer Pair" at 7264.02,3515.39 h72
  text "Hole Tolerance" at 7988.35,3515.39 h72
  text "172" at 5661.16,3391.07 h60
  text "18.00mil (0.457mm)" at 5993.16,3391.07 h60
  text "PTH" at 6629.72,3391.07 h60
  text "Round" at 6888.86,3391.07 h60
  text "Top Layer - Bottom Layer" at 7264.02,3391.07 h60
  text "18" at 5661.16,3266.75 h60
  text "40.00mil (1.016mm)" at 5993.16,3266.75 h60
  text "PTH" at 6629.72,3266.75 h60
  text "Round" at 6888.86,3266.75 h60
  text "Top Layer - Bottom Layer" at 7264.02,3266.75 h60
  text "10" at 5661.16,3142.43 h60
  text "40.16mil (1.020mm)" at 5993.16,3142.43 h60
  text "PTH" at 6629.72,3142.43 h60
  text "Round" at 6888.86,3142.43 h60
  text "Top Layer - Bottom Layer" at 7264.02,3142.43 h60
  text "200 Total" at 5661.16,3018.11 h60
  text ".Layer_Name" at 577,-850.08 h60
M17 Embedded Cavity:
  text ".Layer_Name" at 577,-850.08 h60
M18 Embedded Assembly:
  text ".Layer_Name" at 577,-850.08 h60
M19 Embedded Keepout:
  text ".Layer_Name" at 577,-850.08 h60

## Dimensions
0,-391.59 to 1000,-391.59 on M2 Board Dimensions
0,8.41 to 0,1771.65 on M2 Board Dimensions
0,8.41 to 5413.39,0 on M2 Board Dimensions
